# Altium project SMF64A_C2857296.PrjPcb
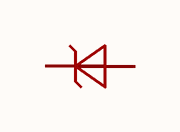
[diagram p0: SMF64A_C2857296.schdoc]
1 sheet, 1 parts. Net scope: global (net labels, ports and power ports of the same name join across sheets).

## Sheet SMF64A_C2857296.schdoc
size 127 x 101 mm

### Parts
D?  smf64a_c2857296  [SOD-123FL_L2.7-W1.8-LS3.7-RD]  (value not drawn)

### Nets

Not connected (* = marked no-connect by the designer): D? 1 2

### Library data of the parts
D? = smf64a_c2857296: 极性:单向;反向截止电压(Vrwm):64V;钳位电压:103V;峰值脉冲电流(Ipp):1.9A;峰值脉冲功率(Ppp):200W@10/1000us;击穿电压(VBR):71.1V;; Manufacturer: JSMSEMI(杰盛微); ManufacturerPart: SMF64A; AddInBom: yes; ModelId: 86f9151e155e4fe2af0c4f2e0a80302e; ModelName: SOD-123FL_L2.8-W1.8-H1.1-LS3.6; ModelTransform: 141.732,70.866,0,180,0,0,0,0,0; Polarity: 单向; Reverse Stand-Off Voltage (Vrwm): 64V; Clamping Voltage: 103V; Peak Pulse Current (Ipp): 1.9A; Voltage - Breakdown: 71.1V; Reverse Leakage Current (Ir): 1uA; Number of Channels: 单路; Type: TVS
